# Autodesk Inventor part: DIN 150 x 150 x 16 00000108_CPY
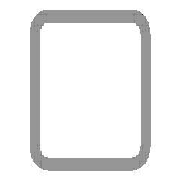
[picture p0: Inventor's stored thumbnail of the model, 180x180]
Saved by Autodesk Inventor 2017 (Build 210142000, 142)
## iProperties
Created: 2017-11
Part Number: DIN 150 x 150 x 16 00000108_CPY
Material: Steel, Mild
Description: Cold formed welded structural hollow sections of non-alloy and fine grain structural steel
Document SubType Name: Modeling
Standard: DIN
Designer: iusti
Standard Revision: 2006-07
Standards Organization: DIN
Language: en-US
Size Designation: 150 x 150 x 16
Categories: <MemberInstance><Categories><Category DisplayName="Structural Shapes" InternalName="089c4875-fa83-4c05-b084-43b9cc11f5ed" Mnemonic="GRDR"><CategoryParameter Dis
Stock Number: 150 x 150 x 16
Mass: 58696.3 g
Surface Area: 9558.04 cm^2
Volume: 7477.24 cm^3
Density: 7.85 g/cm^3
Appearance: Semi-Polished
IsCustomPart: 1
G_W: 150.000 mm
G_H: 150.000 mm
G_L: 1150.000 mm
+D0655DDE-97F9-4B99-A490-E36C02108510+CUTDETAIL1: Miter 45.00 deg
+B95BDB02-C4C2-4ECB-9363-19BA39C44CCB+CUTDETAIL2: Miter 45.00 deg
_CCFamilyMember: 76
_CCFamilyDisplayName: DIN EN 10219-2 (Square Hollow Section - Cold Formed) - Cold formed welded structural hollow sections of non-alloy and fine grain structural steel
_FrameMemberDoc: Frame Member File
_Version: 15.0.0
_GetPNFromCC: 1
Author: iusti
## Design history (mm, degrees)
node "Start plane"
node "End plane"
sketch "Sketch"
  geometry: L1 (-75, -27)-(-75, 27); L2 (-27, 75)-(27, 75); L3 (75, 27)-(75, -27); L4 (27, -75)-(-27, -75); L5 (-27, 59)-(27, 59); L6 (59, 27)-(59, -27); L7 (27, -59)-(-27, -59); L8 (-59, -27)-(-59, 27); L9 (0, 118.918)-(0, -118.918) reference; L10 (-118.918, 0)-(118.918, 0) reference; A1 r 48 centre (-27, -27) between (-75, -27) and (-27, -75); A2 r 48 centre (-27, 27) between (-27, 75) and (-75, 27); A3 r 48 centre (27, 27) between (75, 27) and (27, 75); A4 r 48 centre (27, -27) between (27, -75) and (75, -27); A5 r 32 centre (-27, 27) between (-27, 59) and (-59, 27); A6 r 32 centre (27, 27) between (59, 27) and (27, 59); A7 r 32 centre (27, -27) between (27, -59) and (59, -27); A8 r 32 centre (-27, -27) between (-59, -27) and (-27, -59)
  constraints: 16 end point, 16 point on circle, 8 centre point, 8 tangent, 4 parallel, 3 equal radius, 2 perpendicular, 7 other
  dimensions: "d7" = 48 radius of A1 (= G_IR); "d10" = 150 distance between parallel lines of L2 L4 (= G_H); "d11" = 150 distance between parallel lines of L1 L3 (= G_W); "d12" = 16 distance between parallel lines of L3 L6 (= G_T); "d15" = 75 distance between parallel lines of L2 L10 (= 0.5 x d10); "d16" = 75 distance between parallel lines of L9 L3 (= 0.5 x d11)
extrude "Body" new body sketch "Sketch" stored distance "d3" = 1150 (= G_L); taper "d4" = 0 deg
node "Driven Length"
  sketch "Sketch3"
    geometry: L1 (0, 0)-(10, 0) reference
    constraints: 2 end point, 1 horizontal
  workplane "Work Plane3"
  sketch "Sketch4"
    geometry: L1 (-2, -75)-(12, -75) reference; L2 (-2, 1075)-(12, 1075) reference
    dimensions: "d18" = 1150 distance between parallel lines of L1 L2 (derived)
workplane "Work Plane4"
split "Split1"
workplane "Work Plane5"
split "Split2"
body "Solid1"
other parameters: "G_W" = 150 [user parameter; used in 1 equation term], "G_H" = 150 [user parameter; used in 1 equation term], "G_T" = 16 [user parameter; used in 1 equation term], "G_IR" = 48 [user parameter; used in 1 equation term], "G_L" = 1150 (= d18) [user parameter; used in 1 equation term], "G_OFFSET_START" = 75 [user parameter; used in 1 equation term], "G_OFFSET_END" = 75 [user parameter; used in 1 equation term], "d13" = -75 (= -G_OFFSET_START), "d14" = 1075 (= G_OFFSET_END + B_L), "d17" = 90 deg
